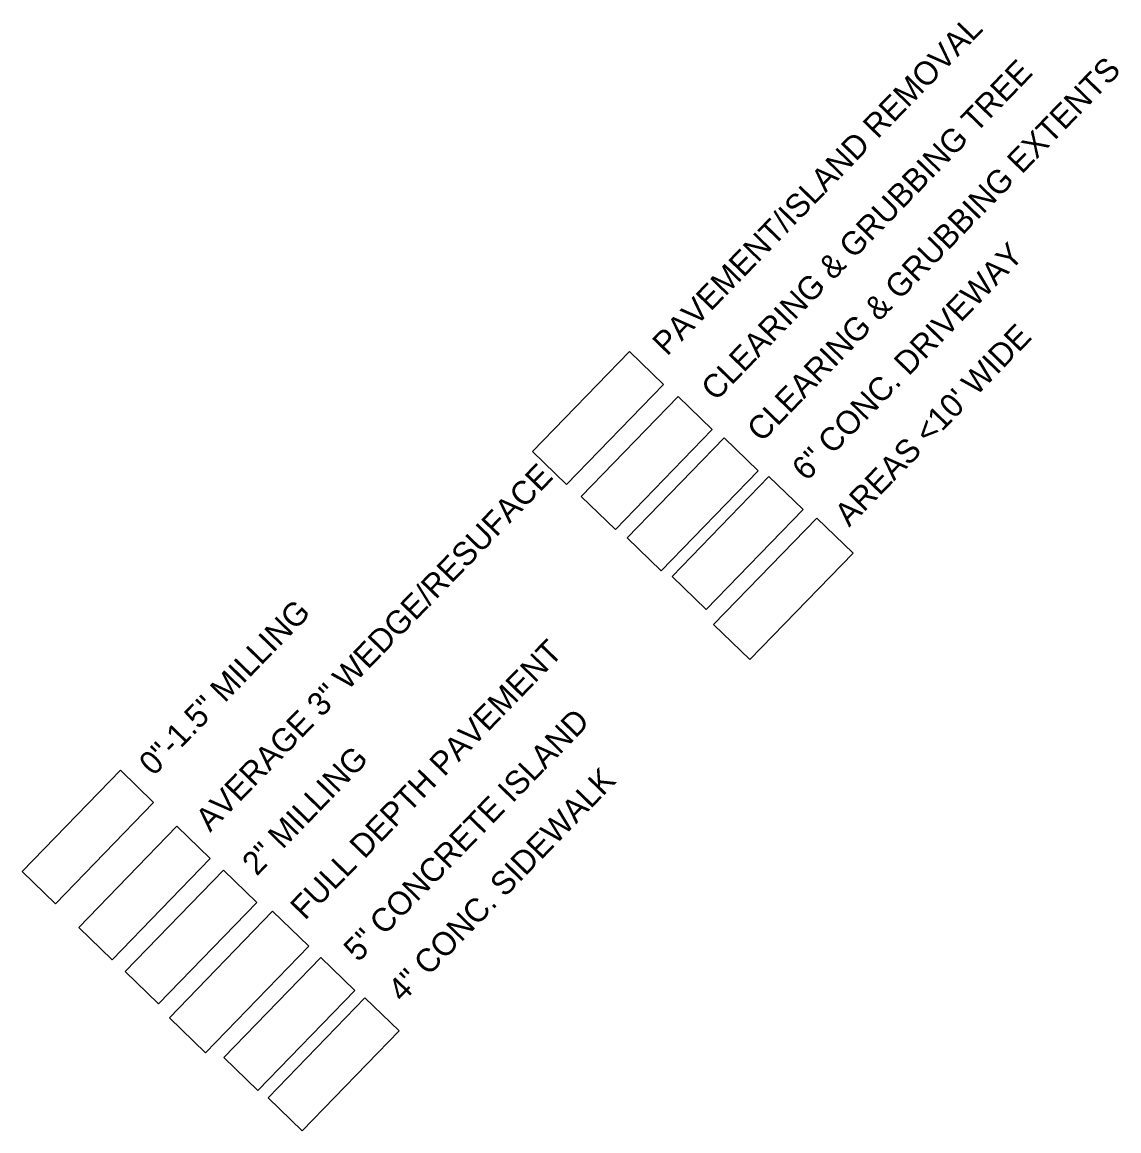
# Model space of a CAD drawing. Extents: x 2008176 to 2196580, y 76380 to 884625.
# Drawn here: x 2174876 to 2175813, y 77663 to 78611 of the extents above; entities that cross this region are included whole.
import ezdxf

# ---------------------------------------------------------------- set-up
doc = ezdxf.new("R2010")
doc.units = 0
for name, color, linetype in [('Exist Property Iron Pin Cogo Comment', 7, 'Continuous'), ('Exist Roads EOP Text', 7, 'Continuous'), ('Exist Roads EOT Leader', 7, 'Continuous'), ('Exist Structure Minor Pipes RCP 15 Inch Leader', 7, 'Continuous'), ('Exist Structure Minor Pipes RCP 15 Inch Text', 7, 'Continuous'), ('Exist Structure Minor Pipes RCP 18 Inch Leader', 7, 'Continuous'), ('Exist Structure Minor Storm Sewer Manhole Leader', 7, 'Continuous'), ('Exist Utilities Other Pole Text', 7, 'Continuous'), ('Exist Vegetation Woods Line', 7, 'Continuous'), ('Raster_Level_0', 7, 'Continuous')]:
    doc.layers.add(name, color=color, linetype=linetype)

msp = doc.modelspace()

# ---------------------------------------------------------------- linework, layer by layer
at = {"layer": 'Exist Property Iron Pin Cogo Comment'}
msp.add_lwpolyline([(2174924.22, 77837.11), (2175008.15, 77923.7), (2175036.62, 77896.1), (2174952.69, 77809.51)], close=True, dxfattribs=at)
at = {"layer": 'Exist Roads EOP Text'}
msp.add_lwpolyline([(2175001.75, 77759.97), (2175090.02, 77851.04), (2175120.93, 77821.08), (2175032.67, 77730.01)], close=True, dxfattribs=at)
at = {"layer": 'Exist Roads EOT Leader'}
msp.add_lwpolyline([(2175431.5, 78137.19), (2175514.36, 78222.68), (2175543.47, 78194.45), (2175460.62, 78108.97)], close=True, dxfattribs=at)
at = {"layer": 'Exist Structure Minor Pipes RCP 15 Inch Leader'}
msp.add_lwpolyline([(2175312.25, 78244.19), (2175395.1, 78329.68), (2175424.22, 78301.45), (2175341.37, 78215.97)], close=True, dxfattribs=at)
at = {"layer": 'Exist Structure Minor Pipes RCP 15 Inch Text'}
msp.add_lwpolyline([(2175086.09, 77691.52), (2175168.94, 77777), (2175198.06, 77748.78), (2175115.2, 77663.29)], close=True, dxfattribs=at)
at = {"layer": 'Exist Structure Minor Pipes RCP 18 Inch Leader'}
msp.add_lwpolyline([(2175048.23, 77726.1), (2175131.09, 77811.58), (2175160.21, 77783.36), (2175077.35, 77697.87)], close=True, dxfattribs=at)
at = {"layer": 'Exist Structure Minor Storm Sewer Manhole Leader'}
msp.add_lwpolyline([(2175353.89, 78205.6), (2175436.74, 78291.09), (2175465.86, 78262.86), (2175383, 78177.38)], close=True, dxfattribs=at)
at = {"layer": 'Exist Utilities Other Pole Text'}
msp.add_lwpolyline([(2175393.07, 78170.44), (2175475.93, 78255.93), (2175505.04, 78227.71), (2175422.19, 78142.22)], close=True, dxfattribs=at)
at = {"layer": 'Exist Vegetation Woods Line'}
for points in [[(2174875.88, 77884.99), (2174959.81, 77971.58), (2174988.29, 77943.98), (2174904.36, 77857.39)], [(2174964, 77799.58), (2175047.93, 77886.17), (2175076.41, 77858.57), (2174992.48, 77771.98)]]:
    msp.add_lwpolyline(points, close=True, dxfattribs=at)
at = {"layer": 'Raster_Level_0'}
msp.add_lwpolyline([(2175467.03, 78096.17), (2175555.3, 78187.24), (2175586.21, 78157.27), (2175497.94, 78066.21)], close=True, dxfattribs=at)

# ---------------------------------------------------------------- texts
at = {"layer": 'Exist Property Iron Pin Cogo Comment'}
msp.add_text('AVERAGE 3" WEDGE/RESUFACE', height=20, rotation=45.89434, dxfattribs=at).set_placement((2175036.6, 77918.05))
at = {"layer": 'Exist Roads EOP Text'}
msp.add_text('FULL DEPTH PAVEMENT', height=20, rotation=45.89434, dxfattribs=at).set_placement((2175117.66, 77842.7))
at = {"layer": 'Exist Roads EOT Leader'}
msp.add_text('6" CONC. DRIVEWAY', height=20, rotation=45.89434, dxfattribs=at).set_placement((2175546.49, 78217.99))
at = {"layer": 'Exist Structure Minor Pipes RCP 15 Inch Leader'}
msp.add_text('PAVEMENT/ISLAND REMOVAL', height=20, rotation=45.89434, dxfattribs=at).set_placement((2175427.24, 78324.99))
at = {"layer": 'Exist Structure Minor Pipes RCP 15 Inch Text'}
msp.add_text('4" CONC. SIDEWALK', height=20, rotation=45.89434, dxfattribs=at).set_placement((2175201.08, 77772.31))
at = {"layer": 'Exist Structure Minor Pipes RCP 18 Inch Leader'}
msp.add_text('5" CONCRETE ISLAND', height=20, rotation=45.89434, dxfattribs=at).set_placement((2175163.22, 77806.89))
at = {"layer": 'Exist Structure Minor Storm Sewer Manhole Leader'}
msp.add_text('CLEARING & GRUBBING TREE', height=20, rotation=45.89434, dxfattribs=at).set_placement((2175468.88, 78286.4))
at = {"layer": 'Exist Utilities Other Pole Text'}
msp.add_text('CLEARING & GRUBBING EXTENTS', height=20, rotation=45.89434, dxfattribs=at).set_placement((2175508.06, 78251.24))
at = {"layer": 'Exist Vegetation Woods Line'}
for s, p in [('0"-1.5" MILLING', (2174988.26, 77965.93)), ('2" MILLING', (2175076.38, 77880.52))]:
    msp.add_text(s, height=20, rotation=45.89434, dxfattribs=at).set_placement(p)
at = {"layer": 'Raster_Level_0'}
msp.add_text("AREAS <10' WIDE", height=20, rotation=45.89434, dxfattribs=at).set_placement((2175582.93, 78178.89))

doc.saveas('drawing.dxf')
